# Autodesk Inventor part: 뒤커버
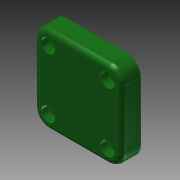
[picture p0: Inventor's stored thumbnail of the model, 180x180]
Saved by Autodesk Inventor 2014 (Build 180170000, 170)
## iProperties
Created: 2018-07
Part Number: 뒤커버
Material: 알루미늄 6061
Document SubType Name: Modeling
Designer: mduedu
Density: 1 g/cm^3
Appearance: 매끄러움 - 짙은 산림 녹색
Author: mduedu
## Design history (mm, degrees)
sketch "스케치1"
  geometry: C1 r 16 at (0, 0); 1 further point
  constraints: 1 centre point, 1 coincident
  dimensions: "d0" = 32 diameter of C1
extrude "돌출1" new body sketch "스케치1" distance "d1" = 3; taper "d2" = 0 deg
sketch "스케치2"
  geometry: L1 (-25, -25)-(25, -25); L2 (25, -25)-(25, 25); L3 (25, 25)-(-25, 25); L4 (-25, 25)-(-25, -25); L5 (-25, -25)-(25, 25); L6 (25, -25)-(-25, 25); 1 further point
  constraints: 12 end point, 2 midpoint, 2 parallel, 1 horizontal, 1 perpendicular
  dimensions: "d3" = 50 distance of L3.end L2.end; "d4" = 50 distance of L2.end L1.end
extrude "돌출2" join sketch "스케치2" distance "d5" = 11; taper "d6" = 0 deg
hole "구멍1" diameter "d9" = 25; stored, may be unused: countersink angle "d13" = 90 deg, drill point angle "d15" = 0 deg; dims "d7" = 10, "d8" = 10, "d10" = 6, "d11" = 4, "d12" = 2, "d14" = 3
fillet "모깎기2" dims "d26" = 3
fillet "모깎기3" dims "d27" = 8
sketch "스케치5"
  geometry: L1 (25, -17)-(25, 17) reference; L2 (17, 25)-(-17, 25) reference; L3 (-25, 17)-(-25, -17) reference; L4 (-17, -25)-(17, -25) reference; A1 r 8 centre (17, -17) between (17, -25) and (25, -17) reference; A2 r 8 centre (17, 17) between (25, 17) and (17, 25) reference; A3 r 8 centre (-17, 17) between (-17, 25) and (-25, 17) reference; A4 r 8 centre (-17, -17) between (-25, -17) and (-17, -25) reference; 5 further points
  constraints: 4 coincident
hole "구멍2" sketch "스케치5" at (-17, 17), (17, 17), (17, -17), (-17, -17) diameter "d28" = 4.5; stored, may be unused: countersink angle "d32" = 90 deg, drill point angle "d34" = 0 deg; dims "d29" = 6, "d30" = 8, "d31" = 4.6, "d33" = 3
fillet "모깎기4" dims "d35" = 3
chamfer "모따기2" distance "d36" = 1; stored, may be unused: second distance "d37" = 2, angle "d38" = 45 deg
node "솔리드1"
node "투영된 루프1"
